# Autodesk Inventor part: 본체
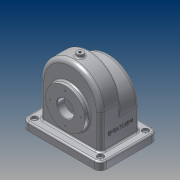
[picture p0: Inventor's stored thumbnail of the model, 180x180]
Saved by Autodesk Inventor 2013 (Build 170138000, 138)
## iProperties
Created: 2017-11
Part Number: 본체
Material: 알루미늄 6061
Document SubType Name: Modeling
Designer: Administrator
Density: 2.71 g/cm^3
Mass: 1096 g
Surface Area: 1234.93 cm^2
Volume: 404.429 cm^3
Author: Administrator
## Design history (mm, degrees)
sketch "스케치1"
  geometry: L1 (-58, -57)-(58, -57); L2 (58, -57)-(58, 23); L3 (-58, -57)-(-58, 23); A1 r 58 centre (0, 0) between (58, 0) and (-58, 0); A2 r 58 centre (0, 23) between (58, 23) and (-58, 23); 1 further point
  constraints: 6 end point, 4 point on circle, 2 centre point, 2 point on line, 2 tangent, 1 coincident, 1 horizontal, 1 parallel, 1 perpendicular, 1 vertical alignment
  dimensions: "d2" = 58 radius of A1; "d3" = 116 diameter of A2; "d4" = 80 distance from line of L1 A2.centre; "d6" = 57 distance from line of L1 point (0, 0)
extrude "돌출1" new body sketch "스케치1" distance "d7" = 38; taper "d8" = 0 deg
extrude "돌출2" join sketch "스케치1" distance "d9" = 38; taper "d10" = 0 deg
feature "쉘1" dims "d11" = 5
sketch "스케치2"
  geometry: L1 (-58, -57)-(58, -57) reference; C1 r 16 at (0, 8); C2 r 31 at (0, 8); A1 r 58 centre (0, 0) between (58, 0) and (-58, 0) reference
  constraints: 2 centre point, 1 coincident, 1 vertical alignment
  dimensions: "d12" = 32 diameter of C1; "d13" = 62 diameter of C2; "d14" = 65 distance from line of L1 C1.centre
extrude "돌출3" cut sketch "스케치2" stored distance "d15" = 38; taper "d16" = 0 deg
extrude "돌출4" join sketch "스케치2" distance "d17" = 10; taper "d18" = 0 deg
sketch "스케치3"
  geometry: L1 (116, 0)-(116, -76) reference; L2 (0, 0)-(116, 0) reference; L3 (0, -76)-(0, 0) reference; L4 (116, -76)-(0, -76) reference; L5 (-5, -93)-(121, -93); L6 (133, -81)-(133, 5); L7 (121, 17)-(-5, 17); L8 (-17, 5)-(-17, -81); L9 (-17, -93)-(133, 17); L10 (133, -93)-(-17, 17); A1 r 12 centre (-5, 5) between (-5, 17) and (-17, 5); A2 r 12 centre (121, 5) between (133, 5) and (121, 17); A3 r 12 centre (121, -81) between (121, -93) and (133, -81); A4 r 12 centre (-5, -81) between (-17, -81) and (-5, -93); 3 further points
  constraints: 12 end point, 8 point on circle, 8 point on line, 8 tangent, 4 centre point, 3 equal radius, 3 midpoint, 2 parallel, 1 coincident, 1 horizontal, 1 perpendicular
  dimensions: "d19" = 150 distance of L9.end L10.end; "d21" = 110 distance of L10.start L9.end; "d22" = 12 radius of A1
extrude "돌출5" join sketch "스케치3" distance "d23" = 15; taper "d24" = 0 deg
sketch "스케치4"
  geometry: C1 r 16 at (0, 8) reference; C2 r 37.5 at (0, 8); 1 further point
  constraints: 1 centre point, 1 coincident
  dimensions: "d25" = 75 diameter of C2
extrude "돌출6" join sketch "스케치4" distance "d27" = 9; taper "d28" = 0 deg
sketch "스케치5"
  geometry: A1 r 12 centre (121, -5) between (121, -17) and (133, -5) reference; A2 r 12 centre (121, 81) between (133, 81) and (121, 93) reference; A3 r 12 centre (-5, 81) between (-5, 93) and (-17, 81) reference; A4 r 12 centre (-5, -5) between (-17, -5) and (-5, -17) reference; 1 further point
hole "구멍1" sketch "스케치5" at (-5, -5), (121, -5), (121, 81), (-5, 81) diameter "d29" = 5; stored, may be unused: countersink angle "d33" = 90 deg, drill point angle "d35" = 118 deg; dims "d30" = 6, "d31" = 12, "d32" = 5, "d34" = 8
node "작업 평면1"
sketch "스케치6"
  geometry: L1 (75, -43)-(75, 43) reference; L2 (58, 38)-(-58, 38) reference; C1 r 6 at (0, 19); 1 further point
  constraints: 1 centre point
  dimensions: "d37" = 75 distance from line of C1.centre L1; "d38" = 19 distance from line of C1.centre L2; "d39" = 12 diameter of C1
extrude "돌출7" join sketch "스케치6" stored distance "d40" = 9; taper "d41" = 0 deg
hole "구멍2" diameter "d44" = 4.459; stored, may be unused: countersink angle "d48" = 90 deg, drill point angle "d50" = 0 deg; dims "d42" = 10, "d43" = 10, "d45" = 6, "d46" = 12, "d47" = 5, "d49" = 8
sketch "스케치7"
  geometry: C1 r 16 at (0, 0) reference; 2 further points
  constraints: 1 vertical alignment
  dimensions: "d51" = 29 distance of C1.centre point (0, 29)
sketch "스케치8"
  geometry: C1 r 16 at (0, 0) reference; 2 further points
  constraints: 1 vertical alignment
  dimensions: "d52" = 26 distance of C1.centre point (0, 26)
hole "구멍3" sketch "스케치7" diameter "d53" = 2.459; stored, may be unused: countersink angle "d57" = 90 deg, drill point angle "d59" = 118 deg; dims "d54" = 6, "d55" = 12, "d56" = 5, "d58" = 8
hole "구멍4" sketch "스케치8" diameter "d60" = 2.459; stored, may be unused: countersink angle "d64" = 90 deg, drill point angle "d66" = 118 deg; dims "d61" = 6, "d62" = 12, "d63" = 5, "d65" = 8
fillet "모깎기2" dims "d71" = 8
fillet "모깎기1" dims "d70" = 3
chamfer "모따기1" distance "d72" = 1; stored, may be unused: second distance "d73" = 2, angle "d74" = 45 deg
sketch "스케치9"
  geometry: L1 (-8, 65)-(-8, 0) reference; L2 (-13, -15)-(73, -15) reference; 2 further points
  constraints: 1 other
  dimensions: "d75" = 38 distance from line of point (30, 25) L1; "d76" = 40 distance from line of L2 point (30, 25)
feature "엠보싱1" sketch "스케치9" dims "d77" = 0.5, "d78" = 0
node "솔리드1"
pattern_circular "원형 패턴1" dims angle "d68" = 360 deg
other parameters: "d36" = 87
